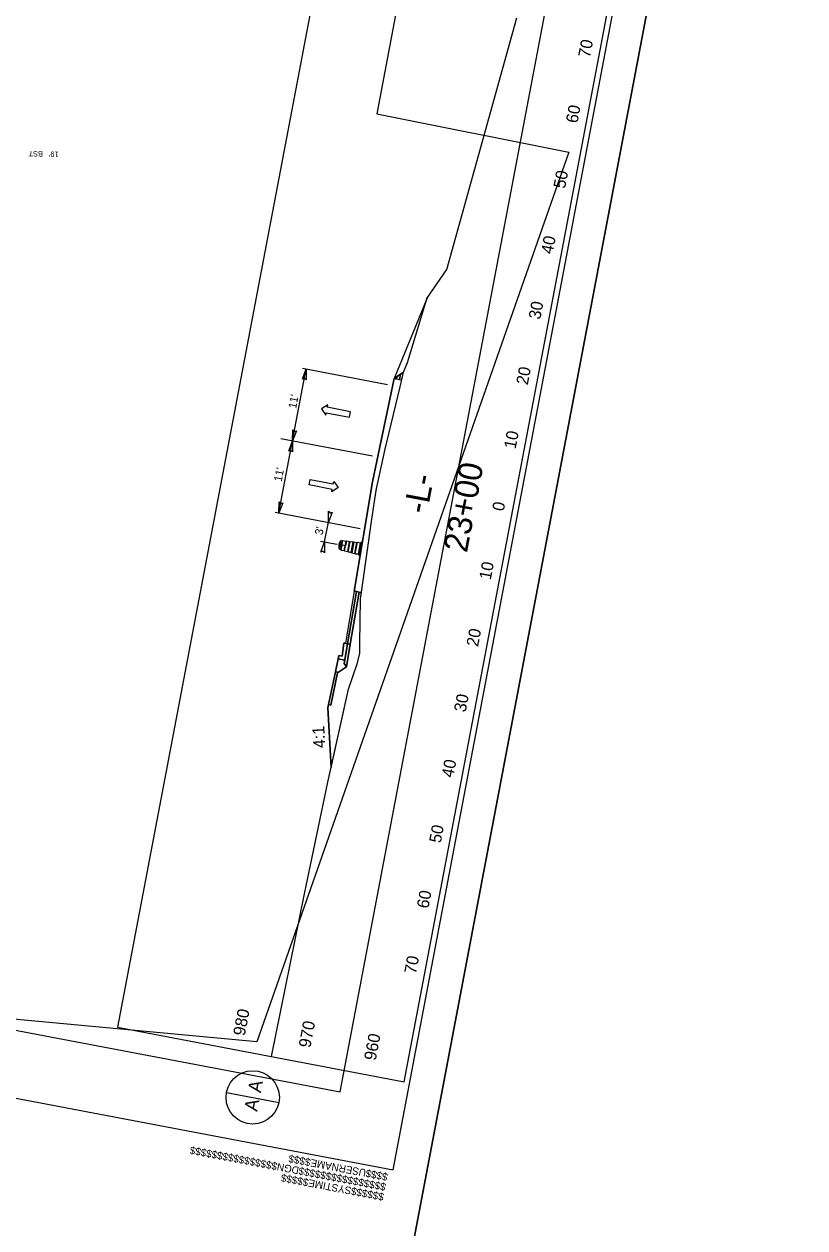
# Model space of a CAD drawing. Extents: x 1615680 to 1617075, y 898420 to 901376.
# Drawn here: x 1616489 to 1617075, y 899426 to 900330 of the extents above; entities that cross this region are included whole.
import ezdxf

# ---------------------------------------------------------------- set-up
doc = ezdxf.new("R2010")
doc.units = 0
for name, color, linetype in [('Default', 7, 'Continuous'), ('DEV BORDER CELL', 7, 'Continuous'), ('DEV DRUM SECTIONAL VIEW CELL', 7, 'Continuous'), ('Exist XS Ground Line', 7, 'Continuous'), ('Gray Area Fill Shapes', 7, 'Continuous'), ('North Arrow', 7, 'Continuous'), ('Old_Level_11', 7, 'Continuous'), ('Prop CMT Pvmt Course 2', 7, 'Continuous'), ('Prop CMT Pvmt Course 3', 7, 'Continuous'), ('Prop CMT Subgrade Earthwork', 7, 'Continuous'), ('Prop Conc 4in Sidewalk', 7, 'Continuous'), ('Prop Conc Curb and Gutter', 7, 'Continuous'), ('Prop Dimension Text', 7, 'Continuous'), ('Prop XS Elevation Labels', 7, 'Continuous'), ('Prop XS Finish Grade', 7, 'Continuous'), ('Prop XS Label Text', 7, 'Continuous'), ('Prop XS Offset Labels', 7, 'Continuous'), ('Prop XS Station Labels', 7, 'Continuous'), ('Scratch_Level_0', 7, 'Continuous'), ('Scratch_Level_9', 7, 'Continuous'), ('Sheet Clip Boundary CELL', 7, 'Continuous'), ('Sheet Cross Section CELL', 7, 'Continuous'), ('Sheet Plot Border Outside CELL', 7, 'Continuous')]:
    doc.layers.add(name, color=color, linetype=linetype)

msp = doc.modelspace()

# ---------------------------------------------------------------- linework, layer by layer
at = {"layer": 'Default'}
for p, q in [((1616641.15, 899527.69), (1616676.55, 899520.97)), ((1616641.15, 899527.68), (1616680.44, 899520.23))]:
    msp.add_line(p, q, dxfattribs=at)
for points in [[(1616698.17, 900063.04), (1616701.05, 900070.74), (1616700.94, 900062.47), (1616699.72, 900063.75)], [(1616693.67, 900024.4), (1616690.79, 900016.7), (1616690.89, 900024.97), (1616692.12, 900023.69)], [(1616687.91, 900009), (1616690.79, 900016.7), (1616690.69, 900008.43), (1616689.46, 900009.72)], [(1616683.41, 899970.37), (1616680.53, 899962.67), (1616680.63, 899970.94), (1616681.86, 899969.65)], [(1616720.49, 899963.33), (1616717.61, 899955.63), (1616717.71, 899963.9), (1616718.94, 899962.61)], [(1616711.93, 899933.19), (1616714.81, 899940.89), (1616714.71, 899932.62), (1616713.48, 899933.91)]]:
    msp.add_lwpolyline(points, close=True, dxfattribs=at)
msp.add_circle((1616660.8, 899523.96), 20, dxfattribs=at)
at = {"layer": 'DEV BORDER CELL'}
msp.add_line((1616766.32, 899469.67), (1616766.32, 899469.67), dxfattribs=at)
msp.add_lwpolyline([(1616014.55, 901139.21), (1615734.74, 899665.53), (1616766.32, 899469.67), (1617046.12, 900943.35)], close=True, dxfattribs=at)
at = {"layer": 'DEV DRUM SECTIONAL VIEW CELL'}
for p, q in [((1616726.9, 899935.41), (1616728.06, 899941.56)), ((1616727.18, 899934.81), (1616728.55, 899942.01)), ((1616728.06, 899941.56), (1616727.34, 899941.7)), ((1616728.55, 899942.01), (1616730.86, 899941.57)), ((1616729.49, 899934.37), (1616730.86, 899941.57)), ((1616729.84, 899934.13), (1616731.28, 899941.68)), ((1616730.86, 899941.57), (1616731.28, 899941.68)), ((1616731.28, 899941.68), (1616733.58, 899941.24)), ((1616732.15, 899933.69), (1616733.58, 899941.24)), ((1616732.5, 899933.44), (1616734, 899941.34)), ((1616733.58, 899941.24), (1616734, 899941.34)), ((1616734, 899941.34), (1616736.31, 899940.9)), ((1616734.81, 899933), (1616736.31, 899940.9)), ((1616735.16, 899932.75), (1616736.73, 899941)), ((1616736.31, 899940.9), (1616736.73, 899941)), ((1616736.73, 899941), (1616739.04, 899940.56)), ((1616737.47, 899932.32), (1616739.04, 899940.56)), ((1616737.82, 899932.07), (1616739.46, 899940.66)), ((1616739.04, 899940.56), (1616739.46, 899940.66)), ((1616739.46, 899940.66), (1616741.77, 899940.23)), ((1616741.17, 899930.8), (1616743.04, 899940.62)), ((1616743.04, 899940.62), (1616742.65, 899940.69)), ((1616726.9, 899935.41), (1616726.18, 899935.54)), ((1616726.24, 899937.13), (1616726.21, 899937.13)), ((1616726.82, 899940.2), (1616726.79, 899940.21)), ((1616727.18, 899934.81), (1616729.49, 899934.37)), ((1616729.49, 899934.37), (1616729.84, 899934.13)), ((1616729.84, 899934.13), (1616732.15, 899933.69)), ((1616732.15, 899933.69), (1616732.5, 899933.44)), ((1616732.5, 899933.44), (1616734.81, 899933)), ((1616734.81, 899933), (1616735.16, 899932.75)), ((1616735.16, 899932.75), (1616737.47, 899932.32)), ((1616737.47, 899932.32), (1616737.82, 899932.07)), ((1616737.82, 899932.07), (1616740.13, 899931.63)), ((1616740.13, 899931.63), (1616741.77, 899940.23)), ((1616740.14, 899931.63), (1616740.49, 899931.38)), ((1616740.48, 899931.33), (1616742.19, 899940.38)), ((1616741.77, 899940.23), (1616742.18, 899940.33)), ((1616741.17, 899930.8), (1616740.79, 899930.87))]:
    msp.add_line(p, q, dxfattribs=at)
for points in [[(1616731.28, 899941.68), (1616730.56, 899937.9), (1616726.71, 899938.63), (1616726.77, 899938.95), (1616726.83, 899939.17), (1616726.88, 899939.37), (1616726.93, 899939.53), (1616726.98, 899939.7), (1616727.03, 899939.85), (1616727.05, 899939.92), (1616727.05, 899939.98), (1616727.02, 899940.06), (1616726.97, 899940.12), (1616726.92, 899940.17), (1616726.86, 899940.2), (1616726.79, 899940.21), (1616726.7, 899940.22), (1616726.62, 899940.19), (1616726.57, 899940.16), (1616726.53, 899940.11), (1616726.5, 899940.08), (1616726.48, 899940.03), (1616726.44, 899939.91), (1616726.4, 899939.78), (1616726.36, 899939.65), (1616726.32, 899939.52), (1616726.27, 899939.35), (1616726.22, 899939.16), (1616726.19, 899939.02), (1616726.16, 899938.89), (1616726.13, 899938.74), (1616725.65, 899938.83), (1616725.69, 899939.06), (1616725.73, 899939.23), (1616725.8, 899939.48), (1616725.84, 899939.64), (1616725.9, 899939.83), (1616725.96, 899940.03), (1616726.05, 899940.27), (1616726.14, 899940.51), (1616726.25, 899940.78), (1616726.36, 899941.01), (1616726.46, 899941.2), (1616726.51, 899941.29), (1616726.55, 899941.38), (1616726.62, 899941.46), (1616726.7, 899941.54), (1616726.77, 899941.58), (1616726.86, 899941.64), (1616726.95, 899941.67), (1616727.05, 899941.7), (1616727.14, 899941.71), (1616727.23, 899941.71), (1616727.31, 899941.71), (1616727.34, 899941.7), (1616728.06, 899941.56), (1616728.16, 899941.69), (1616728.22, 899941.76), (1616728.28, 899941.82), (1616728.36, 899941.89), (1616728.45, 899941.96), (1616728.51, 899941.99), (1616728.55, 899942.01), (1616730.86, 899941.57)], [(1616732.15, 899933.69), (1616733.58, 899941.24), (1616734, 899941.34), (1616736.31, 899940.9), (1616736.73, 899941), (1616735.16, 899932.75), (1616734.81, 899933), (1616732.5, 899933.44)], [(1616737.47, 899932.32), (1616739.04, 899940.56), (1616739.46, 899940.66), (1616741.77, 899940.23), (1616742.18, 899940.33), (1616742.2, 899940.42), (1616742.23, 899940.48), (1616742.27, 899940.55), (1616742.32, 899940.61), (1616742.37, 899940.64), (1616742.44, 899940.67), (1616742.51, 899940.69), (1616742.56, 899940.7), (1616742.62, 899940.7), (1616742.65, 899940.69), (1616743.04, 899940.62), (1616741.17, 899930.8), (1616740.79, 899930.87), (1616740.73, 899930.89), (1616740.67, 899930.91), (1616740.62, 899930.95), (1616740.58, 899930.99), (1616740.55, 899931.02), (1616740.51, 899931.09), (1616740.48, 899931.15), (1616740.47, 899931.23), (1616740.47, 899931.27), (1616740.48, 899931.33), (1616740.49, 899931.38), (1616740.14, 899931.63), (1616737.82, 899932.07)], [(1616729.84, 899934.13), (1616730.56, 899937.9), (1616726.71, 899938.63), (1616726.67, 899938.44), (1616726.65, 899938.3), (1616726.63, 899938.15), (1616726.61, 899938), (1616726.59, 899937.83), (1616726.58, 899937.65), (1616726.57, 899937.46), (1616726.56, 899937.34), (1616726.54, 899937.27), (1616726.5, 899937.22), (1616726.44, 899937.17), (1616726.39, 899937.14), (1616726.33, 899937.12), (1616726.28, 899937.12), (1616726.17, 899937.14), (1616726.12, 899937.17), (1616726.06, 899937.21), (1616726.02, 899937.27), (1616725.99, 899937.35), (1616725.98, 899937.41), (1616725.99, 899937.55), (1616726, 899937.75), (1616726.04, 899938.14), (1616726.08, 899938.42), (1616726.11, 899938.63), (1616726.13, 899938.74), (1616725.65, 899938.83), (1616725.61, 899938.63), (1616725.57, 899938.37), (1616725.54, 899938.1), (1616725.51, 899937.82), (1616725.5, 899937.55), (1616725.49, 899937.25), (1616725.5, 899936.9), (1616725.5, 899936.7), (1616725.53, 899936.37), (1616725.54, 899936.23), (1616725.56, 899936.14), (1616725.59, 899936.03), (1616725.63, 899935.94), (1616725.71, 899935.82), (1616725.79, 899935.74), (1616725.87, 899935.68), (1616725.96, 899935.62), (1616726.05, 899935.58), (1616726.18, 899935.54), (1616726.9, 899935.41), (1616726.91, 899935.33), (1616726.93, 899935.25), (1616726.98, 899935.15), (1616727.03, 899935.04), (1616727.08, 899934.95), (1616727.18, 899934.81), (1616729.49, 899934.37)]]:
    msp.add_lwpolyline(points, close=True, dxfattribs=at)
for centre, radius, start, end in [((1616734.34, 899937.18), 8.85, 152.30015, 186.19859), ((1616727.2, 899940.93), 0.783, 79.24937, 152.30015), ((1616729.2, 899940.83), 1.35, 118.73583, 146.94336), ((1616742.58, 899940.3), 0.392, 79.24937, 169.24937), ((1616726.32, 899936.31), 0.783, 186.19859, 259.24937), ((1616734.82, 899937.09), 8.85, 160.57536, 177.92338), ((1616726.26, 899937.4), 0.274, 177.92338, 259.24937), ((1616726.29, 899937.4), 0.274, 259.24937, 357.39812), ((1616726.74, 899939.94), 0.274, 79.24937, 160.57536), ((1616735.4, 899936.98), 8.85, 161.10062, 177.39812), ((1616726.77, 899939.94), 0.274, 341.10062, 79.24937), ((1616728.22, 899935.68), 1.35, 191.55539, 219.76292), ((1616740.86, 899931.26), 0.392, 169.24937, 259.24937)]:
    msp.add_arc(centre, radius, start, end, dxfattribs=at)
at = {"layer": 'Exist XS Ground Line'}
msp.add_lwpolyline([(1616674.94, 899554.66), (1616699.81, 899676.84), (1616704.2, 899698.26), (1616717.32, 899760.65), (1616732.84, 899830.33), (1616739.16, 899849.37), (1616741.16, 899857.13), (1616741.24, 899864.66), (1616741.71, 899898.18), (1616743.2, 899908.54), (1616750.01, 899956.29), (1616752.98, 899976.16), (1616753.7, 899980.9), (1616754.96, 899986.6), (1616760.03, 900009.46), (1616771.46, 900057.37), (1616774.05, 900068.31), (1616777, 900075.68), (1616791.56, 900123.37), (1616791.63, 900123.51), (1616806.66, 900145.46), (1616859.02, 900334.16)], dxfattribs=at)
at = {"layer": 'Gray Area Fill Shapes'}
for p, q in [((1616791.56, 900123.37), (1616767.12, 900063.6)), ((1616767.12, 900063.6), (1616774.05, 900068.32)), ((1616774.05, 900068.32), (1616767.12, 900063.6)), ((1616774.05, 900068.32), (1616771.72, 900066.73)), ((1616771.72, 900066.73), (1616774.05, 900068.32)), ((1616772.68, 900062.54), (1616774.05, 900068.31)), ((1616774.05, 900068.31), (1616774.05, 900068.32)), ((1616767.12, 900063.6), (1616767.24, 900063.68)), ((1616769.23, 900065.04), (1616767.24, 900063.68)), ((1616767.24, 900063.68), (1616769.23, 900065.04)), ((1616768.86, 900063.27), (1616769.23, 900065.04)), ((1616769.23, 900065.04), (1616768.86, 900063.27)), ((1616768.86, 900063.27), (1616770.91, 900062.88)), ((1616771.72, 900066.73), (1616769.23, 900065.04)), ((1616769.23, 900065.04), (1616771.72, 900066.73)), ((1616770.91, 900062.88), (1616771.72, 900066.73)), ((1616771.72, 900066.73), (1616770.91, 900062.88)), ((1616770.91, 900062.88), (1616772.68, 900062.54)), ((1616770.91, 900062.88), (1616772.68, 900062.54)), ((1616737, 899903.96), (1616730.37, 899864.8)), ((1616738.63, 899903.65), (1616732.01, 899864.49)), ((1616740.68, 899903.26), (1616734.05, 899864.1)), ((1616734.05, 899864.1), (1616740.68, 899903.26)), ((1616740.68, 899903.26), (1616738.63, 899903.65)), ((1616738.63, 899903.65), (1616740.68, 899903.26)), ((1616740.68, 899903.26), (1616742.39, 899902.93)), ((1616742.39, 899902.93), (1616740.68, 899903.26)), ((1616740.68, 899903.26), (1616742.39, 899902.93)), ((1616732.01, 899864.49), (1616729.92, 899852.16)), ((1616734.05, 899864.1), (1616731.19, 899847.21)), ((1616732.01, 899864.49), (1616734.05, 899864.1)), ((1616724.94, 899853.11), (1616722.88, 899843.32)), ((1616729.92, 899852.16), (1616724.94, 899853.11)), ((1616724.94, 899853.11), (1616729.92, 899852.16)), ((1616729.92, 899852.16), (1616729.5, 899849.69)), ((1616719.35, 899818.49), (1616724.43, 899842.61)), ((1616722.88, 899843.32), (1616724.53, 899843.06)), ((1616731.19, 899847.21), (1616724.43, 899842.61)), ((1616724.43, 899842.61), (1616731.19, 899847.21)), ((1616724.53, 899843.06), (1616724.43, 899842.61)), ((1616729.5, 899849.69), (1616731.19, 899847.21)), ((1616717.73, 899818.85), (1616717.21, 899816.4)), ((1616717.21, 899816.4), (1616719.78, 899771.67))]:
    msp.add_line(p, q, dxfattribs=at)
for points in [[(1616774.05, 900068.32), (1616777, 900075.68), (1616791.56, 900123.37)], [(1616742.39, 899902.93), (1616743.2, 899908.54), (1616750.01, 899956.29), (1616752.98, 899976.16), (1616753.7, 899980.9), (1616754.96, 899986.6), (1616760.03, 900009.46), (1616771.46, 900057.37), (1616774.05, 900068.31), (1616774.05, 900068.32)], [(1616737, 899903.96), (1616736.89, 899903.98), (1616750.78, 899986.02), (1616767.12, 900063.6)], [(1616767.12, 900063.6), (1616750.78, 899986.02), (1616736.89, 899903.98), (1616737, 899903.96)], [(1616767.24, 900063.68), (1616767.22, 900063.58), (1616767.94, 900063.44), (1616768.86, 900063.27)], [(1616719.78, 899771.67), (1616732.84, 899830.33), (1616739.16, 899849.37), (1616741.16, 899857.13), (1616741.24, 899864.66), (1616741.71, 899898.18), (1616742.39, 899902.93)], [(1616730.37, 899864.8), (1616732.01, 899864.49), (1616738.63, 899903.65), (1616737.71, 899903.82), (1616737, 899903.96)], [(1616737, 899903.96), (1616737.71, 899903.82), (1616738.63, 899903.65)], [(1616742.39, 899902.93), (1616742.39, 899902.93)], [(1616742.39, 899902.93), (1616742.39, 899902.93)], [(1616729.92, 899852.16), (1616732.01, 899864.49), (1616730.37, 899864.8), (1616729.14, 899865.04), (1616727.87, 899855.1), (1616725.41, 899855.56), (1616724.94, 899853.11)], [(1616731.19, 899847.21), (1616734.05, 899864.1), (1616732.01, 899864.49)], [(1616731.19, 899847.21), (1616729.5, 899849.69), (1616729.92, 899852.16)], [(1616724.43, 899842.61), (1616724.53, 899843.06), (1616722.88, 899843.32), (1616717.73, 899818.85), (1616719.35, 899818.49)], [(1616724.43, 899842.61), (1616719.35, 899818.49), (1616717.73, 899818.85)]]:
    msp.add_lwpolyline(points, dxfattribs=at)
at = {"layer": 'North Arrow'}
msp.add_line((1616750.62, 900005.34), (1616681.91, 900018.39), dxfattribs=at)
at = {"layer": 'Old_Level_11'}
for p, q in [((1616680.53, 899962.67), (1616701.05, 900070.74)), ((1616698.23, 900071.27), (1616762, 900059.16)), ((1616677.71, 899963.2), (1616741.48, 899951.1)), ((1616714.81, 899940.89), (1616717.61, 899955.63)), ((1616711.65, 899941.49), (1616724.13, 899939.12))]:
    msp.add_line(p, q, dxfattribs=at)
at = {"layer": 'Prop CMT Pvmt Course 2'}
msp.add_lwpolyline([(1616737, 899903.96), (1616730.37, 899864.8), (1616730.37, 899864.8), (1616732.01, 899864.49), (1616738.63, 899903.65), (1616738.63, 899903.65), (1616737, 899903.96), (1616737, 899903.96), (1616737, 899903.96)], dxfattribs=at)
at = {"layer": 'Prop CMT Pvmt Course 3'}
for points in [[(1616738.63, 899903.65), (1616732.01, 899864.49), (1616732.01, 899864.49), (1616734.05, 899864.1), (1616740.68, 899903.26), (1616740.68, 899903.26), (1616738.63, 899903.65), (1616738.63, 899903.65), (1616738.63, 899903.65)], [(1616732.01, 899864.49), (1616734.05, 899864.1), (1616731.19, 899847.21), (1616729.5, 899849.69), (1616732.01, 899864.49)]]:
    msp.add_lwpolyline(points, dxfattribs=at)
at = {"layer": 'Prop CMT Subgrade Earthwork'}
for points in [[(1616774.05, 900068.32), (1616767.12, 900063.6)], [(1616734.05, 899864.1), (1616740.68, 899903.26), (1616740.68, 899903.26)], [(1616734.05, 899864.1), (1616731.19, 899847.21)], [(1616731.19, 899847.21), (1616724.43, 899842.61)]]:
    msp.add_lwpolyline(points, dxfattribs=at)
at = {"layer": 'Prop Conc 4in Sidewalk'}
msp.add_lwpolyline([(1616722.88, 899843.32), (1616724.53, 899843.06), (1616719.35, 899818.49), (1616717.73, 899818.85), (1616722.88, 899843.32)], dxfattribs=at)
at = {"layer": 'Prop Conc Curb and Gutter'}
msp.add_lwpolyline([(1616729.14, 899865.04), (1616729.14, 899865.04), (1616729.14, 899865.04), (1616732.01, 899864.49), (1616732.01, 899864.49), (1616729.92, 899852.16), (1616724.94, 899853.11), (1616724.94, 899853.11), (1616725.41, 899855.56), (1616725.41, 899855.56), (1616725.41, 899855.56), (1616727.87, 899855.1), (1616729.14, 899865.04)], dxfattribs=at)
at = {"layer": 'Prop Dimension Text'}
for p, q in [((1616717.13, 900043.82), (1616712.48, 900040.7)), ((1616712.48, 900040.7), (1616715.64, 900035.98)), ((1616716.77, 900041.95), (1616717.13, 900043.82)), ((1616734.18, 900038.65), (1616716.77, 900041.95)), ((1616715.64, 900035.98), (1616715.99, 900037.85)), ((1616715.99, 900037.85), (1616733.4, 900034.54)), ((1616733.4, 900034.54), (1616734.18, 900038.65)), ((1616703.12, 899983.64), (1616703.9, 899987.74)), ((1616703.9, 899987.74), (1616721.31, 899984.44)), ((1616721.31, 899984.44), (1616721.66, 899986.3)), ((1616721.66, 899986.3), (1616724.85, 899981.7)), ((1616720.53, 899980.33), (1616703.12, 899983.64)), ((1616724.85, 899981.7), (1616720.17, 899978.47)), ((1616720.17, 899978.47), (1616720.53, 899980.33))]:
    msp.add_line(p, q, dxfattribs=at)
at = {"layer": 'Prop XS Finish Grade'}
for points in [[(1616791.56, 900123.37), (1616791.56, 900123.37), (1616767.12, 900063.6)], [(1616722.88, 899843.32), (1616724.94, 899853.11), (1616724.94, 899853.11)], [(1616717.21, 899816.4), (1616717.73, 899818.85), (1616717.73, 899818.85)], [(1616719.78, 899771.67), (1616719.78, 899771.67), (1616717.21, 899816.4)]]:
    msp.add_lwpolyline(points, dxfattribs=at)
at = {"layer": 'Scratch_Level_0'}
msp.add_line((1616677.71, 899963.2), (1616741.48, 899951.1), dxfattribs=at)
msp.add_lwpolyline([(1616054.34, 901080.76), (1615793.19, 899705.33), (1616726.52, 899528.12), (1616890.46, 900391.55), (1616774.26, 900413.61), (1616871.48, 900925.61)], close=True, dxfattribs=at)
at = {"layer": 'Scratch_Level_9'}
msp.add_lwpolyline([(1616729.14, 899865.04), (1616730.37, 899864.8)], dxfattribs=at)
at = {"layer": 'Sheet Clip Boundary CELL'}
msp.add_lwpolyline([(1616176.29, 901060.7), (1616913.78, 900900.04), (1616896.28, 900812.91), (1616872.94, 900688.21), (1616835.87, 900695.21), (1616753.94, 900262.18), (1616898.09, 900233.43), (1616663.91, 899565.73), (1616252.62, 899604.04), (1615894.68, 899796.73), (1615981.58, 900932.46), (1616145.94, 900899.57)], close=True, dxfattribs=at)
at = {"layer": 'Sheet Cross Section CELL'}
for p, q in [((1616723.15, 900439.56), (1616559.31, 899576.61)), ((1616774.52, 899535.75), (1616938.37, 900398.7)), ((1616559.31, 899576.61), (1616774.52, 899535.75))]:
    msp.add_line(p, q, dxfattribs=at)
at = {"layer": 'Sheet Plot Border Outside CELL'}
for points in [[(1616760.47, 899304.87), (1615679.78, 899510.06), (1615994.65, 901168.43), (1617075.34, 900963.24)], [(1616760.47, 899304.87), (1617075.34, 900963.24), (1615994.65, 901168.43), (1615679.78, 899510.06)]]:
    msp.add_lwpolyline(points, close=True, dxfattribs=at)

# ---------------------------------------------------------------- texts
at = {"layer": 'Default'}
for s, height, rotation, p in [("19'   BST", 4, 178.72674, (1616515.15, 900233.83)), ("11'", 6, 79.24933, (1616693.38, 900040.65)), ("11'", 6, 79.24933, (1616682.54, 899985.81)), ("3'", 6, 79.24933, (1616713.21, 899945.79)), ('A', 10, 79.25306, (1616666.83, 899527.06)), ('A', 10, 79.25306, (1616664.16, 899513))]:
    msp.add_text(s, height=height, rotation=rotation, dxfattribs=at).set_placement(p)
at = {"layer": 'DEV BORDER CELL'}
for s, p in [('$$$$$$$$$$$$$$$$DGN$$$$$$$$$$$$$$$$', (1616761.22, 899459.32)), ('$$$$USERNAME$$$$', (1616762.63, 899466.77)), ('$$$$$$SYSTIME$$$$$', (1616759.8, 899451.87))]:
    msp.add_text(s, height=5.584, rotation=169.24937, dxfattribs=at).set_placement(p)
at = {"layer": 'Prop XS Elevation Labels'}
for s, p in [('980', (1616654.85, 899569.73)), ('970', (1616704.04, 899560.75)), ('960', (1616753.12, 899551.22))]:
    msp.add_text(s, height=9, rotation=79.24937, dxfattribs=at).set_placement(p)
at = {"layer": 'Prop XS Label Text'}
msp.add_text('4:1', height=9, rotation=93.28561, dxfattribs=at).set_placement((1616715.43, 899786.35))
at = {"layer": 'Prop XS Offset Labels'}
for s, p in [('70', (1616913.89, 900303.91)), ('60', (1616904.57, 900254.78)), ('50', (1616895.24, 900205.66)), ('40', (1616885.91, 900156.54)), ('30', (1616876.59, 900107.42)), ('20', (1616867.26, 900058.29)), ('10', (1616858.13, 900010.23)), ('0', (1616849.27, 899963.55)), ('0', (1616849.27, 899963.55)), ('10', (1616839.48, 899911.98)), ('20', (1616829.95, 899861.8)), ('30', (1616820.63, 899812.68)), ('40', (1616811.3, 899763.56)), ('50', (1616801.97, 899714.44)), ('60', (1616792.65, 899665.31)), ('70', (1616783.32, 899616.19))]:
    msp.add_text(s, height=9, rotation=79.24937, dxfattribs=at).set_placement(p)
at = {"layer": 'Prop XS Station Labels'}
for s, p in [('23+00', (1616821.57, 899932.26)), ('-L-', (1616791.59, 899961.3))]:
    msp.add_text(s, height=18, rotation=79.24937, dxfattribs=at).set_placement(p)
at = {"layer": 'Scratch_Level_9'}
for p in [(1616837.46, 900256.47), (1616729.14, 899865.04), (1616729.14, 899865.04), (1616727.87, 899855.1), (1616722.88, 899843.32), (1616717.73, 899818.85), (1616719.78, 899771.67)]:
    msp.add_text('X', height=0.00125, rotation=79.24937, dxfattribs=at).set_placement(p)

doc.saveas('drawing.dxf')
